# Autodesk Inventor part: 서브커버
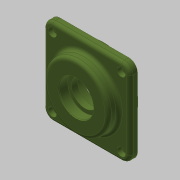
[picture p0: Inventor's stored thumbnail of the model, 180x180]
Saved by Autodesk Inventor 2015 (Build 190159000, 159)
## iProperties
Created: 2018-09
Part Number: 서브커버
Material: 일반
Document SubType Name: Modeling
Designer: mduedu
Density: 1 g/cm^3
Appearance: 올리브 녹색
Mass: 76.2032 g
Surface Area: 197.007 cm^2
Volume: 76.2032 cm^3
Author: mduedu
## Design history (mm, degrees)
sketch "스케치1"
  geometry: L1 (-40, -40)-(40, -40); L2 (40, -40)-(40, 40); L3 (40, 40)-(-40, 40); L4 (-40, 40)-(-40, -40); L5 (-40, -40)-(40, 40); L6 (40, -40)-(-40, 40); 1 further point
  constraints: 12 end point, 2 midpoint, 2 parallel, 1 horizontal, 1 perpendicular
  dimensions: "d0" = 80 distance of L3.end L2.end; "d1" = 80 distance of L2.end L1.end
extrude "돌출1" new body sketch "스케치1" distance "d2" = 7; taper "d3" = 0 deg
sketch "스케치2"
  geometry: C1 r 30 at (0, 0); 1 further point
  constraints: 1 centre point, 1 coincident
  dimensions: "d4" = 60 diameter of C1
extrude "돌출2" join sketch "스케치2" distance "d5" = 10; taper "d6" = 0 deg
sketch "스케치3"
  geometry: C1 r 32.5 at (0, 0); 1 further point
  constraints: 1 centre point, 1 coincident
  dimensions: "d7" = 65 diameter of C1
extrude "돌출3" join sketch "스케치3" distance "d8" = 9; taper "d9" = 0 deg
sketch "스케치4"
  geometry: L1 (-32.5, -9)-(32.5, -9) reference; L2 (30, 17)-(-30, 17) reference; L3 (0, 17)-(0, -9); L4 (0, -9)-(20, -9); L5 (20, -9)-(20, 3); L6 (20, 3)-(0, 3); L7 (0, 3)-(0, -9); L8 (0, 3)-(12.5, 3); L9 (12.5, 3)-(12.5, 8.7); L10 (12.5, 8.7)-(0, 8.7); L11 (0, 8.7)-(0, 3); L12 (0, 8.7)-(16, 8.7); L13 (16, 8.7)-(16, 17); L14 (16, 17)-(0, 17); L15 (0, 17)-(0, 8.7); 1 further point
  constraints: 26 end point, 6 parallel, 3 horizontal, 3 perpendicular, 2 midpoint, 1 point on line
  dimensions: "d10" = 12 distance of L4.end L5.end; "d12" = 8.3 distance of L12.end L13.end; "d13" = 32 diameter of L13 L3; "d14" = 25 diameter of L9 L3; "d15" = 40 diameter of L5 L3
revolve "회전1" sketch "스케치4" stored, may be unused: angle "d16" = 90 deg
fillet "모깎기1" dims "d17" = 8
fillet "모깎기2" dims "d18" = 3
fillet "모깎기3" dims "d19" = 3
chamfer "모따기1" distance "d20" = 0.8; stored, may be unused: second distance "d21" = 2, angle "d22" = 30 deg
chamfer "모따기2" distance "d23" = 1; stored, may be unused: second distance "d24" = 2, angle "d25" = 30 deg
fillet "모깎기4" dims "d26" = 0.3
sketch "스케치5"
  geometry: A1 r 8 centre (-32, 32) between (-32, 40) and (-40, 32) reference; A2 r 8 centre (-32, -32) between (-40, -32) and (-32, -40) reference; A3 r 8 centre (32, -32) between (32, -40) and (40, -32) reference; A4 r 8 centre (32, 32) between (40, 32) and (32, 40) reference; 5 further points
  constraints: 4 coincident
hole "구멍1" sketch "스케치5" at (-32, 32), (32, 32), (32, -32), (-32, -32) diameter "d27" = 4.5; stored, may be unused: countersink angle "d31" = 90 deg, drill point angle "d33" = 118 deg; dims "d28" = 6, "d29" = 8, "d30" = 4.4, "d32" = 8
node "솔리드1"
